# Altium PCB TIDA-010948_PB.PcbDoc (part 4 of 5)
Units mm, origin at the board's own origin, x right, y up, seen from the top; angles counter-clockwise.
Board outline 140 x 180 mm, 4 copper layers (Top Layer, Mid-Layer 1, Mid-Layer 2, Bottom Layer), stack 1.554 mm thick; 481 components, 274 nets, 1278 pads, 301 vias.
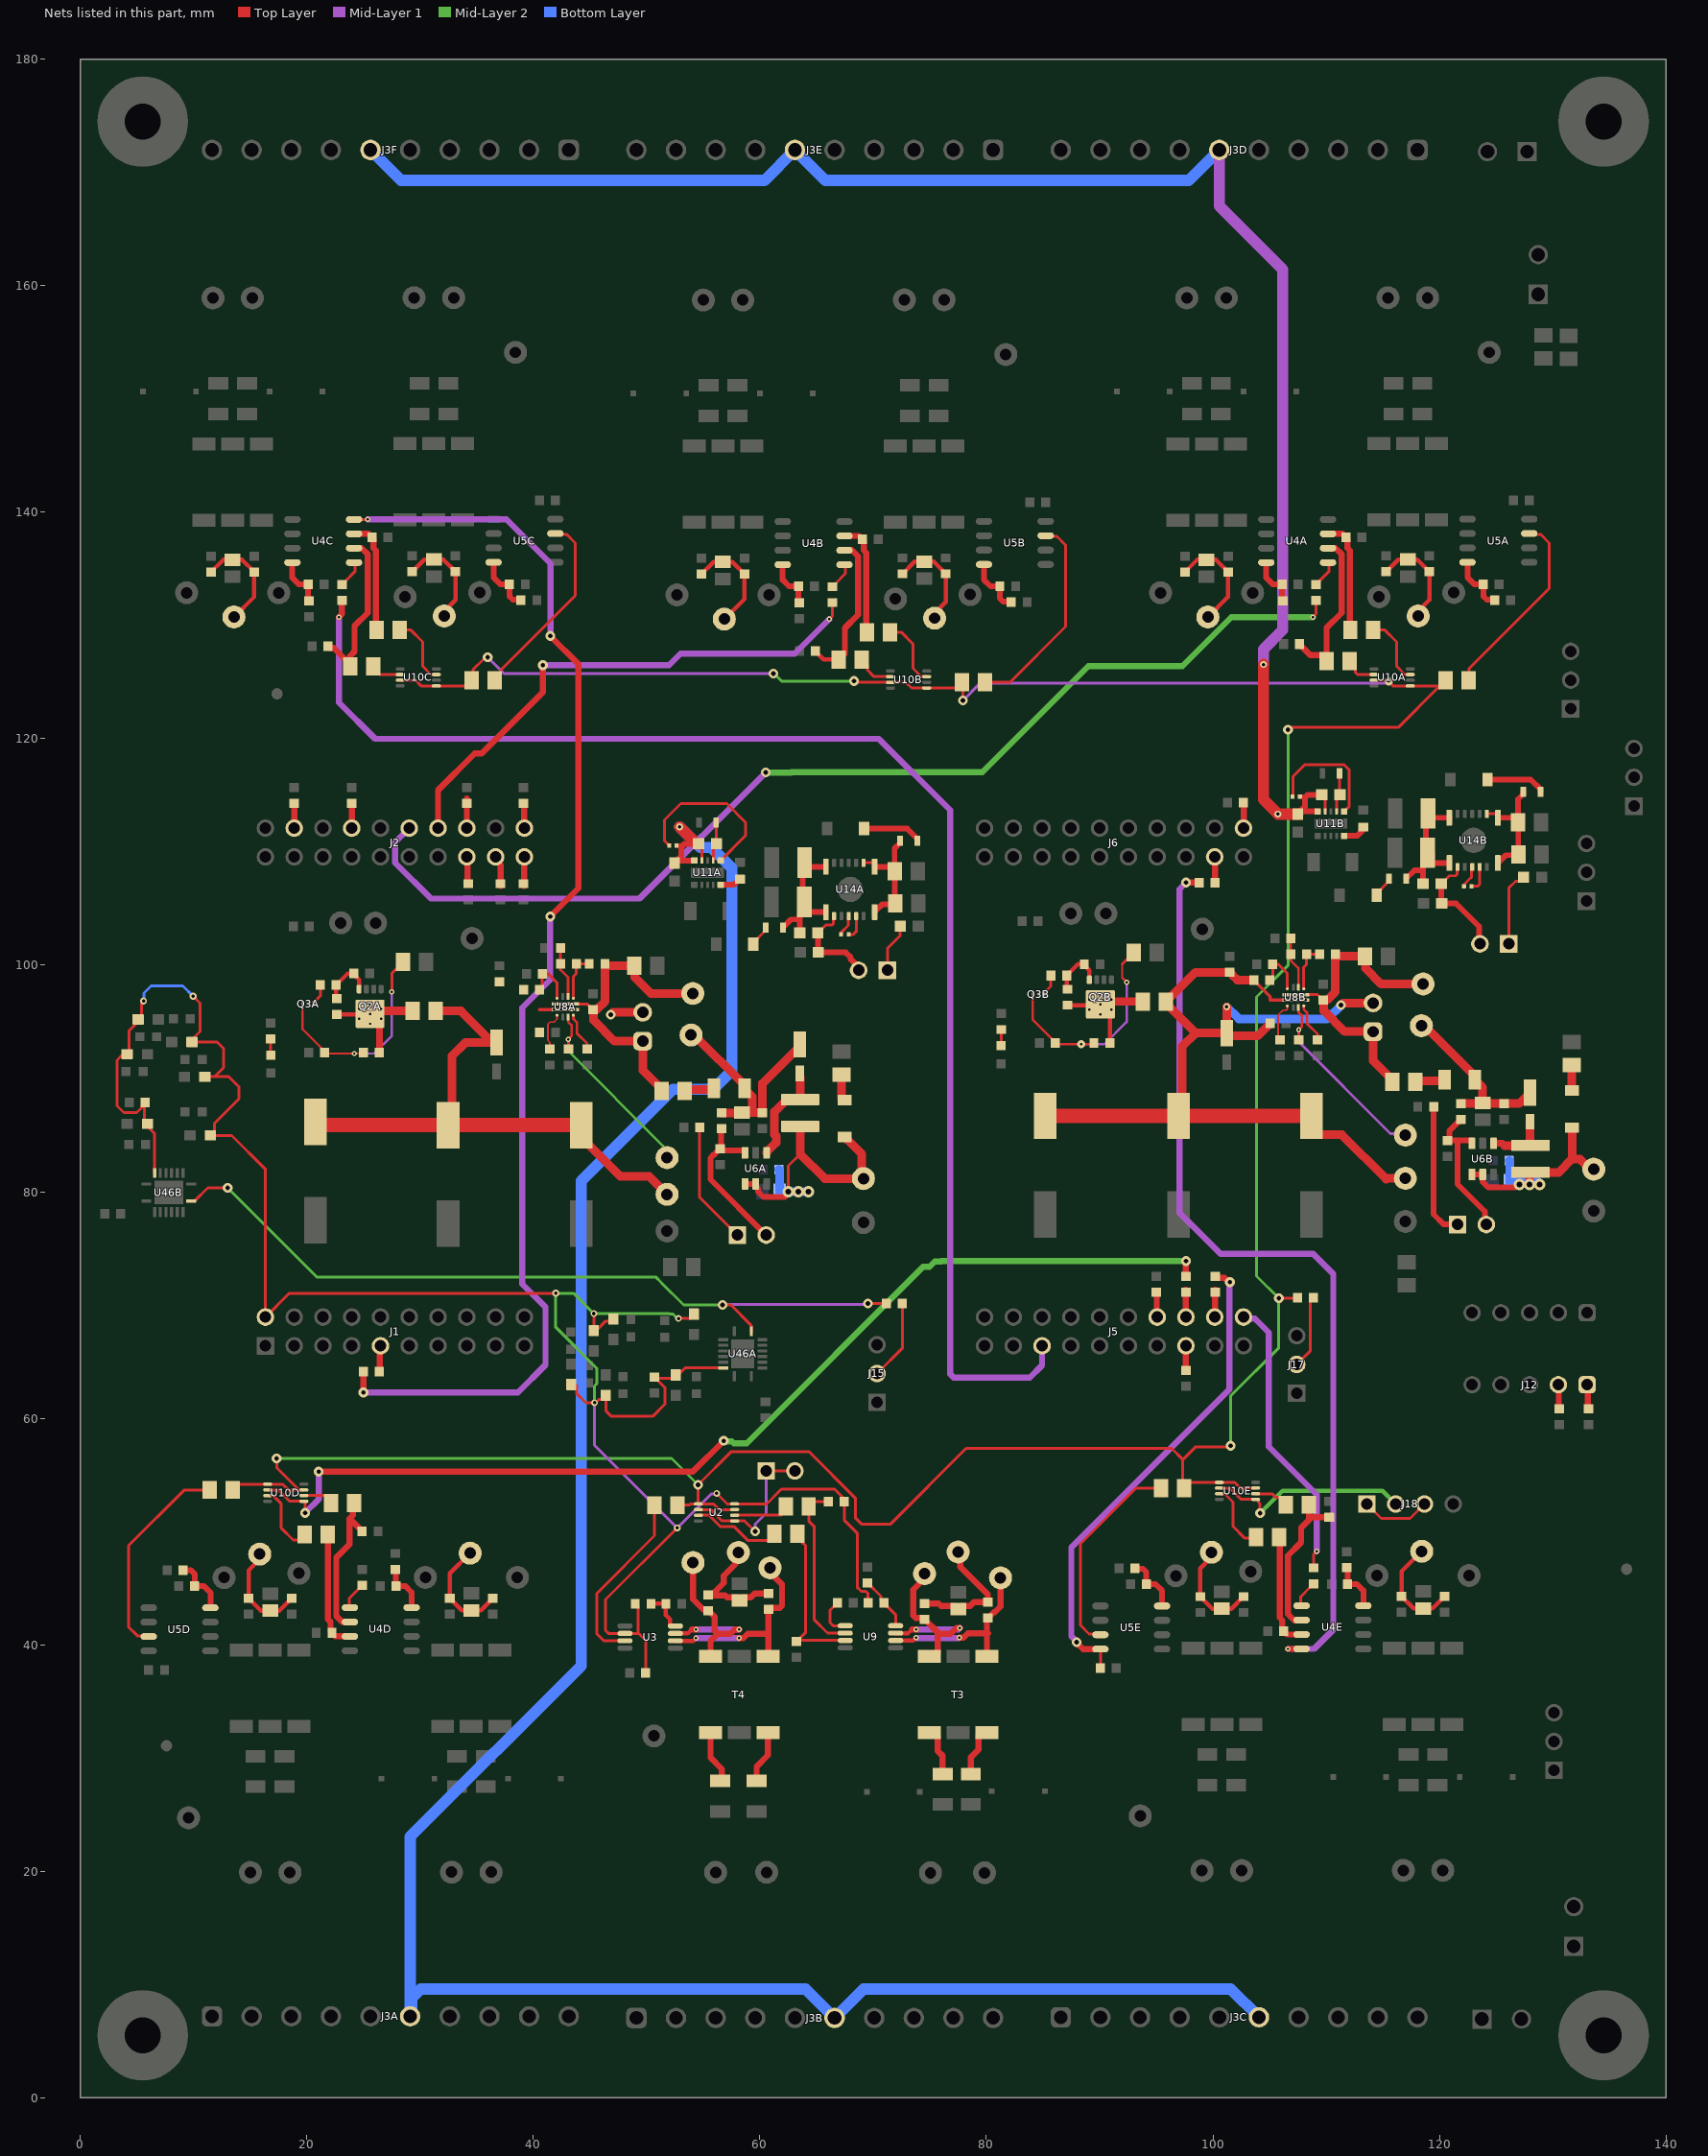
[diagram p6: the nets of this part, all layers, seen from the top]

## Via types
v1: diameter 0.457/0.457/0.457/0.457 (per signal layer), hole 0.203, Top Layer to Bottom Layer, tented both sides, 68 vias
v2: diameter 0.864, hole 0.406, Top Layer to Mid-Layer 1, 51 vias
v3: diameter 0.5, hole 0.2, Top Layer to Bottom Layer, 40 vias
v4: diameter 0.864, hole 0.406, Top Layer to Bottom Layer, 40 vias
v5: diameter 0.7, hole 0.3, Top Layer to Bottom Layer, 36 vias
v6: diameter 0.61, hole 0.3, Top Layer to Bottom Layer, 29 vias
v7: diameter 1.524, hole 0.762, Top Layer to Bottom Layer, tented both sides, 12 vias
v8: diameter 0.203, hole 0.203, Top Layer to Bottom Layer, tented both sides, 8 vias
v9: diameter 1.016, hole 0.508, Top Layer to Bottom Layer, tented both sides, 6 vias
v10: diameter 0.61, hole 0.3, Top Layer to Mid-Layer 1, 3 vias
v11: diameter 0.457, hole 0.203, Top Layer to Mid-Layer 1, tented both sides, 2 vias
v12: diameter 0.5, hole 0.2, Top Layer to Bottom Layer, tented both sides, 2 vias
v13: diameter 0.7, hole 0.203, Top Layer to Mid-Layer 1, tented both sides, 1 vias
v14: diameter 0.7, hole 0.254, Top Layer to Bottom Layer, 1 vias
v15: diameter 0.7, hole 0.254, Top Layer to Mid-Layer 1, 1 vias
v16: diameter 0.457/0.457 (per signal layer), hole 0.203, Top Layer to Mid-Layer 1, tented both sides, 1 vias

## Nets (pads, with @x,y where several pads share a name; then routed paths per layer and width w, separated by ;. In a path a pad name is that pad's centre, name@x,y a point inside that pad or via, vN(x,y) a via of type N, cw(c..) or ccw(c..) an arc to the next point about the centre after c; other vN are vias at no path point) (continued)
LP_5V0: C2A.1 C2B.1 J1.21 R1A.2 R1B.2 R2A.2 R2B.2 R3A.2 R3B.2 R4A.2 R4B.2 R5A.2 R5B.2 R6A.2 R6B.2 R10.2 R15.1 R30.1 R33.2 U2.8 U3.2 U46A.15 U46B.15 | length 204.2
  Top Layer w0.254: v6(5.568,96.847) 5.568,96.751 5.407,96.59 5.407,95.339 5.284,95.215 5.284,95.19 5.011,94.917 4.986,94.917 4.291,94.222 4.291,92.208 4.32,92.18 4.32,92.163 4.204,92.048 3.666,92.048 3.238,91.62 3.238,87.586 3.833,86.991 4.978,86.991 5.447,87.459 5.447,87.609 C2B.1@5.72,87.882 5.632,87.795 5.632,86.073 5.72,85.986 5.72,85.961 5.993,85.688 6.018,85.688 6.546,85.16 U46B.15@6.546,81.656 ; v6(9.947,97.263) 10.567,96.643 10.567,94.158 9.649,93.24 9.649,93.215 12.067,93.215 12.639,92.644 12.639,90.958 11.836,90.155 ; R5B.2@10.787,90.155 11.836,90.155 ; v6(41.975,71.035) 18.445,71.035 J1.21@16.337,68.927 16.337,81.973 13.357,84.953 11.488,84.953 R6B.2@11.471,84.97 11.503,84.97 11.826,85.293 11.826,86.037 13.999,88.21 13.999,89.265 13.109,90.155 11.836,90.155 ; R3A.2@43.335,63.178 43.608,62.905 43.799,62.905 43.799,62.185 44.621,61.364 45.486,61.364 45.763,61.641 46.072,61.641 46.395,61.964 R2A.2@46.395,62.214 ; v6(45.335,69.241) 45.335,67.543 45.36,67.543 45.992,68.176 45.992,68.201 46.343,68.551 R5A.2@47.065,68.551 ; R2A.2@46.42,62.214 46.42,60.628 46.888,60.161 50.524,60.161 51.63,61.267 51.63,62.676 C2A.1@50.78,63.527 ; R30.1@48.987,43.615 49.26,43.342 49.26,41.016 49.283,40.993 ; R33.2@49.912,37.525 49.912,40.364 49.283,40.993 ; R1A.2@52.564,63.814 52.564,63.639 R1A.2@52.589,63.614 ; v10(52.694,50.309) 46.37,43.985 46.37,41.257 46.635,40.993 U3.2@48.082,40.993 49.283,40.993 ; v6(52.807,68.807) 52.838,68.837 53.845,68.837 53.845,68.818 54.168,69.141 R6A.2@54.168,69.191 ; v10(56.186,53.357) 57.116,52.427 U2.8@57.766,52.427 60.602,52.427 61.9,53.725 66.595,53.725 R10.2@67.551,52.769 ; U46A.15@56.763,64.44 53.39,64.44 52.862,63.912 52.862,63.887 R1A.2@52.589,63.614 ; R10.2@67.444,52.637 67.444,50.993 68.59,49.847 68.59,45.066 68.943,44.713 69.34,44.713 69.553,44.501 R15.1@69.553,43.695 ; C2A.1@50.668,63.614 50.643,63.614 C2A.1@50.668,63.614 ; C2A.1@50.668,63.614 50.693,63.614 C2A.1@50.78,63.527 ; C2A.1@50.78,63.527 52.477,63.527 52.564,63.614 R1A.2@52.589,63.614
  Mid-Layer 1 w0.254: v6(45.39,61.364) 45.39,57.612 v10(52.694,50.309) 55.674,53.289 56.118,53.289 v10(56.186,53.357)
  Mid-Layer 2 w0.254: v6(45.39,61.364) 45.39,62.843 45.584,63.036 45.584,64.419 41.975,68.028 v6(41.975,71.035) 43.541,71.035 v6(45.335,69.241) 51.995,69.241 52.043,69.193 52.325,69.193 52.711,68.807 v6(52.807,68.807)
  Bottom Layer w0.254: v6(5.568,96.847) 5.609,96.888 5.609,97.533 6.244,98.168 9.042,98.168 v6(9.947,97.263)
LS_OE_HIGH: R11.1 U46A.8 U46B.8 | length 70.1
  Top Layer w0.254: U46B.8@9.771,79.181 10.063,79.181 11.23,80.348 v4(13,80.348) ; v4(56.694,69.994) 57.43,69.994 59.225,68.199 59.225,67.678 U46A.8@59.238,67.665 ; v2(69.541,70.133) R11.1@71.171,70.133
  Mid-Layer 1 w0.254: v4(56.694,69.994) 56.763,70.064 69.471,70.064 v2(69.541,70.133)
  Mid-Layer 2 w0.254: v4(13,80.348) 20.905,72.442 50.835,72.442 51.277,72 51.277,71.976 53.259,69.994 v4(56.694,69.994)
NetC8A_1: C8A.1 R16A.2 U4A.8 | length 4.3
  Top Layer w0.508: U4A.8@104.715,135.562 104.715,134.223 105.281,133.657 C8A.1@106.105,133.657 R16A.2@106.105,132.573 ; R16A.2@106.169,132.182 R16A.2@106.333,132.345
NetC8B_1: C8B.1 R16B.2 U4B.8 | length 4.3
  Top Layer w0.508: U4B.8@62.016,135.375 62.016,134.036 62.582,133.47 C8B.1@63.406,133.47 R16B.2@63.406,132.386 ; R16B.2@63.47,131.995 R16B.2@63.633,132.158
NetC8C_1: C8C.1 R16C.2 U4C.8 | length 4.3
  Top Layer w0.508: U4C.8@18.715,135.562 18.715,134.223 19.281,133.657 C8C.1@20.105,133.657 R16C.2@20.105,132.573 ; R16C.2@20.169,132.182 R16C.2@20.333,132.345
NetC8D_1: C8D.1 R16D.2 U4D.8 | length 4.3
  Top Layer w0.508: R16D.2@27.625,46.492 R16D.2@27.789,46.656 ; R16D.2@27.853,46.264 C8D.1@27.853,45.181 28.677,45.181 29.243,44.615 U4D.8@29.243,43.276
NetC8E_1: C8E.1 R16E.2 U4E.8 | length 4.3
  Top Layer w0.508: R16E.2@111.667,46.655 R16E.2@111.831,46.818 ; R16E.2@111.895,46.427 C8E.1@111.895,45.343 112.719,45.343 113.285,44.777 U4E.8@113.285,43.438
NetC9A_1: C9A.1 R18A.2 U5A.8 | length 5.2
  Top Layer w0.508: U5A.8@122.484,135.582 122.484,134.243 123.07,133.657 123.874,133.657 123.874,132.594 124.187,132.28 R18A.2@124.89,132.28
NetC9B_1: C9B.1 R18B.2 U5B.8 | length 5.2
  Top Layer w0.508: U5B.8@79.784,135.395 79.784,134.056 80.371,133.47 81.174,133.47 81.174,132.407 81.488,132.093 R18B.2@82.19,132.093
NetC9C_1: C9C.1 R18C.2 U5C.8 | length 5.2
  Top Layer w0.508: U5C.8@36.484,135.582 36.484,134.243 37.07,133.657 37.874,133.657 37.874,132.594 38.187,132.28 R18C.2@38.89,132.28
NetC9D_1: C9D.1 R18D.2 U5D.8 | length 5.2
  Top Layer w0.508: R18D.2@9.068,46.557 9.771,46.557 10.084,46.244 10.084,45.181 10.888,45.181 11.474,44.594 U5D.8@11.474,43.255
NetC9E_1: C9E.1 R18E.2 U5E.8 | length 5.2
  Top Layer w0.508: R18E.2@93.11,46.72 93.813,46.72 94.126,46.406 94.126,45.343 94.93,45.343 95.516,44.757 U5E.8@95.516,43.418
NetC10A_1: C10A.1 R22A.1 R24A.1 TP21A.1 | length 9.4
  Top Layer w0.381: R22A.1@97.534,134.735 98.603,135.804 C10A.1@99.439,135.804 100.276,135.804 R24A.1@101.344,134.735 101.345,132.536 TP21A.1@99.545,130.736
NetC10B_1: C10B.1 R22B.1 R24B.1 TP21B.1 | length 9.4
  Top Layer w0.381: R22B.1@54.835,134.548 55.904,135.617 56.74,135.617 57.576,135.617 58.645,134.548 58.645,132.349 TP21B.1@56.845,130.549
NetC10C_1: C10C.1 R22C.1 R24C.1 TP21C.1 | length 9.4
  Top Layer w0.381: R22C.1@11.534,134.735 12.603,135.804 C10C.1@13.439,135.804 14.276,135.804 R24C.1@15.344,134.735 15.345,132.536 TP21C.1@13.545,130.736
NetC10D_1: C10D.1 R22D.1 R24D.1 TP21D.1 | length 9.4
  Top Layer w0.381: TP21D.1@34.413,48.102 32.613,46.302 R24D.1@32.614,44.103 33.682,43.034 C10D.1@34.519,43.034 35.355,43.034 R22D.1@36.424,44.103
NetC10E_1: C10E.1 R22E.1 R24E.1 TP21E.1 | length 9.4
  Top Layer w0.381: TP21E.1@118.455,48.264 116.655,46.464 116.655,44.265 117.724,43.196 118.56,43.196 119.397,43.196 R22E.1@120.466,44.265
NetC11A_1: C11A.1 R23A.1 R25A.1 TP22A.1 | length 9
  Top Layer w0.381: R23A.1@115.302,134.755 116.371,135.824 C11A.1@117.208,135.824 118.044,135.824 R25A.1@119.113,134.755 119.113,132.272 118.126,131.285 TP22A.1@118.126,130.838
NetC11B_1: C11B.1 R23B.1 R25B.1 TP22B.1 | length 9
  Top Layer w0.381: R23B.1@72.603,134.568 73.672,135.637 C11B.1@74.508,135.637 75.344,135.637 R25B.1@76.413,134.568 76.413,132.085 75.426,131.098 TP22B.1@75.426,130.651
NetC11C_1: C11C.1 R23C.1 R25C.1 TP22C.1 | length 9
  Top Layer w0.381: R23C.1@29.302,134.755 30.371,135.824 C11C.1@31.208,135.824 32.044,135.824 R25C.1@33.113,134.755 33.113,132.272 32.126,131.285 TP22C.1@32.126,130.838
NetC11D_1: C11D.1 R23D.1 R25D.1 TP22D.1 | length 9
  Top Layer w0.381: TP22D.1@15.832,47.999 15.832,47.552 14.845,46.565 R25D.1@14.845,44.082 15.914,43.013 C11D.1@16.75,43.013 17.587,43.013 R23D.1@18.656,44.082
NetC11E_1: C11E.1 R23E.1 R25E.1 TP22E.1 | length 9
  Top Layer w0.381: TP22E.1@99.874,48.162 99.874,47.715 98.887,46.728 R25E.1@98.887,44.245 99.956,43.176 C11E.1@100.792,43.176 101.629,43.176 R23E.1@102.698,44.245
NetC18A_1: C18A.1 C116A.1 D1A.1 L5A.1 TP27A.1 U6A.4 U6A.5 | length 26.6
  Top Layer w0.254: 62.213,79.535 62.603,79.925 v9(62.51,80.017) 62.51,82.288 63.56,83.337
  Top Layer w0.508: U6A.4@58.68,80.692 U6A.5@59.63,80.692 59.63,80.492 59.826,80.296 59.826,80.034 60.325,79.535 62.213,79.535
  Top Layer w0.762: L5A.1@63.56,85.765 63.56,83.337 65.736,81.161 TP27A.1@69.141,81.161 68.992,81.311 68.992,83.32 67.716,84.597 67.716,84.749 67.639,84.826 D1A.1@67.487,84.826
  Bottom Layer w0.762: C18A.1@61.671,81.938 61.721,81.888 C116A.1@61.721,80.035 ; C116A.1@61.721,80.008 v9(64.288,80.008)
  other v9: 63.399,80.017
NetC18B_1: C18B.1 C116B.1 D1B.1 L5B.1 TP27B.1 U6B.4 U6B.5 | length 19.5
  Top Layer w0.508: U6B.4@122.877,81.52 U6B.5@123.827,81.52 123.827,80.875 124.338,80.363 v9@126.706,80.363
  Top Layer w0.762: v9(127.964,80.641) 127.964,81.621 L5B.1@128.053,81.71 130.551,81.71 131.726,82.886 ; D1B.1@131.726,85.654 131.726,82.886 ; TP27B.1@133.635,81.99 133.291,81.99 132.395,82.886 131.726,82.886
  Bottom Layer w0.762: C18B.1@126.164,82.767 126.214,82.717 C116B.1@126.214,80.863 ; C116B.1@126.214,80.837 v9@128.782,80.837
  other v9: 127.075,80.641 128.853,80.633
NetC21_2: C21.2 T3.6 | length 4.5
  Top Layer w0.54: C21.2@78.617,28.582 78.617,30.049 79.302,30.734 79.302,31.922 79.604,32.223 T3.6@80.048,32.223
NetC22A_1: C22A.1 C120A.1 D3A.1 R28A.2 R31A.1 TP30A.1 | length 20.2
  Top Layer w0.762: TP30A.1@53.919,93.841 54.187,93.841 58.651,89.377 R31A.1@58.651,89.138 ; R28A.2@56.616,86.958 58.371,86.958 C120A.1@58.421,87.008 59.331,87.008 59.331,88.372 R31A.1@58.651,89.052 ; 59.331,86.977 60.207,86.977 C22A.1@60.226,86.958 60.226,89.565 63.524,92.863 D3A.1@63.524,93.008
NetC22B_1: C22B.1 C120B.1 D3B.1 R28B.2 R31B.1 TP30B.1 | length 16
  Top Layer w0.762: TP30B.1@118.562,94.52 TP30B.1@118.413,94.67 118.681,94.67 123.145,90.205 R31B.1@123.145,89.88 123.824,89.201 C120B.1@123.824,87.836 ; R28B.2@121.922,87.786 123.774,87.786 C120B.1@123.824,87.836 ; D3B.1@128.018,88.754 127.05,87.786 C22B.1@125.732,87.786 123.874,87.786 C120B.1@123.824,87.836
NetC23_2: C23.2 T3.4 | length 4.4
  Top Layer w0.54: T3.4@74.968,32.223 75.413,32.223 75.714,31.922 75.714,30.605 76.14,30.179 C23.2@76.14,28.582
NetC24A_1: C24A.1 J11A.1 NT1A.2 NT6A.2 R37A.2 TP33A.1 U8A.5 | length 27.5
  Top Layer w0.254: U8A.5@42.831,96.584 44.736,96.584 45.236,96.084 C24A.1@45.261,96.084
  Top Layer w0.762: C24A.1@45.305,96.065 45.305,95.152 47.154,93.303 J11A.1@49.647,93.303 49.647,90.739 51.339,89.048 NT6A.2@51.339,88.883 ; C24A.1@45.605,96.103 46.321,96.819 R37A.2@46.321,100.119 ; R37A.2@46.321,100.144 R37A.2@46.321,100.119 ; TP33A.1@54.073,97.512 50.376,97.512 48.964,98.924 48.964,99.913 NT1A.2@48.921,99.955 46.486,99.955 R37A.2@46.321,100.119
NetC24B_1: C24B.1 J11B.1 NT1B.2 NT6B.2 R37B.2 TP33B.1 U8B.5 | length 27.5
  Top Layer w0.254: U8B.5@107.325,97.412 109.23,97.412 109.73,96.912 C24B.1@109.755,96.912
  Top Layer w0.762: C24B.1@109.799,96.893 109.799,95.98 111.648,94.131 J11B.1@114.141,94.131 114.141,91.568 115.832,89.877 NT6B.2@115.832,89.711 ; C24B.1@110.099,96.931 110.815,97.647 R37B.2@110.815,100.948 ; R37B.2@110.815,100.973 R37B.2@110.815,100.948 ; TP33B.1@118.566,98.34 114.869,98.34 113.457,99.752 113.457,100.741 NT1B.2@113.415,100.783 110.979,100.783 R37B.2@110.815,100.948
NetC25A_1: C25A.1 U8A.10 | length 3.5
  Top Layer w0.229: U8A.10@43.531,95.584 43.531,95.275 43.831,94.975 43.831,94.003 44.736,93.098 C25A.1@44.736,92.589
NetC25B_1: C25B.1 U8B.10 | length 3.5
  Top Layer w0.229: U8B.10@108.025,96.412 108.025,96.103 108.325,95.803 108.325,94.831 109.23,93.926 C25B.1@109.23,93.417
NetC26A_1: C26A.1 U8A.7 | length 3.6
  Top Layer w0.152: C26A.1@41.439,92.589 41.439,93.199 41.278,93.36 41.278,93.662 41.277,93.663 41.277,94.449 41.278,94.45 41.278,94.805 41.448,94.975 41.803,94.975 42.081,95.253 U8A.7@42.081,95.586
NetC26B_1: C26B.1 U8B.7 | length 3.6
  Top Layer w0.152: C26B.1@105.933,93.417 105.756,93.594 105.756,95.593 106.199,96.036 106.486,96.036 106.575,96.125 U8B.7@106.575,96.412
NetC27A_2: C27A.2 Q2A.4 R44A.1 R46A.2 | length 4.8
  Top Layer w0.381: R44A.1@22.651,97.053 22.589,97.115 R46A.2@22.589,98.258 23.605,99.274 C27A.2@24.05,99.274 ; C27A.2@24.15,99.274 C27A.2@24.05,99.274 ; Q2A.4@24.597,97.893 24.597,98.727 C27A.2@24.05,99.274
NetC27B_2: C27B.2 Q2B.4 R44B.1 R46B.2 | length 4.8
  Top Layer w0.381: R44B.1@87.144,97.882 87.082,97.944 R46B.2@87.082,99.087 88.098,100.103 C27B.2@88.544,100.103 ; C27B.2@88.644,100.103 C27B.2@88.544,100.103 ; Q2B.4@89.09,98.722 89.09,99.556 C27B.2@88.544,100.103
NetC32_1: C32.1 R21.1 R27.1 TP5.1 | length 11.6
  Top Layer w0.54: R27.1@74.522,43.64 75.771,43.64 76.001,43.41 77.244,43.41 C32.1@77.51,43.144 77.79,43.424 78.561,43.424 78.897,43.76 R21.1@80.131,43.76 ; TP5.1@77.51,48.186 77.693,48.003 77.693,46.868 80.132,44.43 R21.1@80.131,43.76
NetC33_1: C33.1 R15.2 U9.8 | length 4.8
  Top Layer w0.254: C33.1@69.482,45.462 69.507,45.462 70.68,44.288 70.68,43.968 R15.2@70.953,43.695 70.953,43.67 71.978,42.645 U9.8@71.978,41.67
NetC34_2: C34.2 T4.6 | length 4.7
  Top Layer w0.54: C34.2@59.709,27.98 59.709,29.231 60.715,30.237 T4.6@60.715,32.218
NetC35_2: C35.2 T4.4 | length 4.7
  Top Layer w0.54: T4.4@55.635,32.218 55.635,30.033 56.645,29.024 56.645,28.136 C35.2@56.488,27.98
NetC36_1: C36.1 R34.1 R35.1 TP11.1 | length 10.5
  Top Layer w0.54: R35.1@55.437,44.39 55.472,44.355 55.755,44.355 56.915,44.355 57.101,44.17 57.922,44.17 C36.1@58.202,43.889 58.482,44.17 59.198,44.17 59.533,44.505 R34.1@60.768,44.505 ; R35.1@55.755,44.39 56.801,45.437 56.801,46.092 57.827,47.118 57.827,47.867 TP11.1@58.102,48.142
NetC37_1: C37.1 R30.2 U3.8 | length 3.9
  Top Layer w0.381: R30.2@50.387,43.615 C37.1@51.699,43.615 51.699,42.618 52.068,42.249 52.068,41.675 52.1,41.643 U3.8@52.532,41.643
NetC46A_2: C46A.2 U11A.5 | length 1.9
  Top Layer w0.508: U11A.5@56.536,107.105 57.689,107.105 58.183,107.599 C46A.2@58.233,107.599
NetC46B_2: C46B.2 U11B.5 | length 1.9
  Top Layer w0.508: U11B.5@111.583,111.432 112.736,111.432 113.23,111.926 C46B.2@113.28,111.926
NetC50A_2: C50A.2 C51A.2 R51A.1 U14A.1 U14A.2 U14A.14 | length 11.2
  Top Layer w0.254: U14A.2@69.153,109.047 70.005,109.047 70.128,108.924 U14A.1@70.128,108.697
  Top Layer w0.5: U14A.14@70.128,104.697 70.826,105.396 72.013,105.396 71.915,105.493 71.915,108.277 C51A.2@71.892,108.3 C51A.2@71.892,108.312 ; U14A.1@70.128,108.697 71.507,108.697 C51A.2@71.892,108.312 ; R51A.1@72.371,110.992 72.371,110.802 71.892,110.323 C51A.2@71.892,108.312
NetC50B_2: C50B.2 C51B.2 R51B.1 U14B.1 U14B.2 U14B.14 | length 11.2
  Top Layer w0.254: U14B.2@124.199,113.374 125.051,113.374 125.174,113.251 U14B.1@125.174,113.024
  Top Layer w0.5: U14B.14@125.174,109.024 125.873,109.723 127.06,109.723 126.962,109.821 126.962,112.604 C51B.2@126.939,112.628 C51B.2@126.939,112.639 ; U14B.1@125.174,113.024 126.554,113.024 C51B.2@126.939,112.639 ; R51B.1@127.417,115.32 127.417,115.129 126.939,114.65 C51B.2@126.939,112.639
NetC59A_1: C59A.1 C60A.2 R41A.2 R52A.2 U14A.7 U14A.8 | length 12.3
  Top Layer w0.5: R52A.2@62.032,103.333 62.748,104.049 63.51,104.049 ; R41A.2@63.51,102.866 63.51,104.049 ; C60A.2@63.775,105.988 C59A.1@63.775,108.697 ; C60A.2@63.92,105.819 C60A.2@63.92,105.606 ; C59A.1@63.986,108.697 U14A.7@65.828,108.697 ; U14A.8@65.828,104.697 64.321,104.697 64.308,105.606 C60A.2@63.92,105.606 ; 63.51,104.049 63.51,104.496 63.92,104.906 C60A.2@63.92,105.606
NetC59B_1: C59B.1 C60B.2 R41B.2 R52B.2 U14B.7 U14B.8 | length 12.3
  Top Layer w0.5: R52B.2@117.079,107.661 117.794,108.376 118.557,108.376 ; R41B.2@118.557,107.193 118.557,108.376 ; C60B.2@118.822,110.316 C59B.1@118.822,113.024 ; C60B.2@118.967,110.146 C60B.2@118.967,109.934 ; C59B.1@119.032,113.024 U14B.7@120.874,113.024 ; U14B.8@120.874,109.024 119.367,109.024 119.354,109.934 C60B.2@118.967,109.934 ; 118.557,108.376 118.557,108.824 118.967,109.234 C60B.2@118.967,109.934
NetD1A_2: D1A.2 NT4A.2 | length 2.5
  Top Layer w0.762: NT4A.2@67.19,90.355 67.19,90.122 67.212,90.101 67.212,88.223 67.334,88.101 D1A.2@67.487,88.101
NetD1B_2: D1B.2 NT4B.2 | length 2.3
  Top Layer w0.762: NT4B.2@131.684,91.183 131.705,91.162 131.705,88.951 D1B.2@131.726,88.929
NetD2A_2: D2A.2 R52A.1 | length 1.9
  Top Layer w0.254: D2A.2@59.422,101.861 59.422,102.014 60.381,102.973 60.381,103.206 R52A.1@60.508,103.333
NetD2B_2: D2B.2 R52B.1 | length 1.9
  Top Layer w0.254: D2B.2@114.468,106.189 114.468,106.341 115.428,107.3 115.428,107.534 R52B.1@115.555,107.661
NetD3A_2: D3A.2 L5A.2 U6A.1 | length 9.1
  Top Layer w0.762: U6A.1@60.58,83.442 60.58,83.48 61.424,84.324 61.424,84.917 61.279,85.063 61.279,87.064 62.35,88.135 L5A.2@63.56,88.135 63.56,90.11 63.524,90.145 D3A.2@63.524,90.448
NetD3B_2: D3B.2 L5B.2 U6B.1 | length 5.5
  Top Layer w0.6: U6B.1@124.777,84.27 125.548,84.27
  Top Layer w0.635: 125.548,84.27 125.738,84.08
  Top Layer w0.762: 125.738,84.08 L5B.2@128.053,84.08 128.018,84.116 D3B.2@128.018,86.194
NetD6A_1: D6A.1 R51A.2 | length 5.2
  Top Layer w0.508: D6A.1@69.21,112.072 73.006,112.072 73.895,111.183 R51A.2@73.895,110.992
NetD6B_1: D6B.1 R51B.2 | length 5.2
  Top Layer w0.508: D6B.1@124.256,116.399 128.052,116.399 128.941,115.51 R51B.2@128.941,115.32
NetD8A_2: D8A.2 R49A.1 | length 1.4
  Top Layer w0.254: D8A.2@16.809,92.073 R49A.1@16.809,93.494
NetD8B_2: D8B.2 R49B.1 | length 1.4
  Top Layer w0.254: D8B.2@81.303,92.902 R49B.1@81.302,94.323
NetJ1_5: J1.5 R50.2 | length 2.3
  Top Layer w0.54: R50.2@26.384,64.129 26.441,64.185 26.441,66.331 J1.5@26.497,66.387
NetJ2_11: J2.11 R57.1 | length 2.2
  Top Layer w0.54: R57.1@39.135,114.29 39.166,114.259 39.166,112.138 J2.11@39.197,112.107
NetJ2_13: J2.13 R54.1 | length 2.6
  Top Layer w0.54: J2.13@34.117,112.107 34.117,114.734
NetJ2_17: J2.17 R32.1 | length 2.2
  Top Layer w0.54: J2.17@23.957,112.107 R32.1@23.957,114.29
NetJ2_19: J2.19 R14.1 | length 2.2
  Top Layer w0.54: J2.19@18.877,112.107 18.879,112.109 R14.1@18.879,114.287
NetJ2_31: J2.31 R56.2 | length 2.6
  Top Layer w0.54: R56.2@39.135,106.987 39.166,107.018 39.166,109.536 J2.31@39.197,109.567
NetJ2_32: J2.32 R55.2 | length 2.8
  Top Layer w0.54: J2.32@36.657,109.567 36.657,109.293 37.094,108.856 R55.2@37.094,106.986
NetJ2_33: J2.33 R53.2 | length 2.4
  Top Layer w0.54: J2.33@34.117,109.567 34.18,109.504 34.18,107.262 R53.2@34.242,107.199
NetJ5_48: J5.48 R59.2 | length 2.2
  Top Layer w0.54: R59.2@97.617,64.216 J5.48@97.617,66.387
NetJ5_67: J5.67 R58.1 | length 2.2
  Top Layer w0.54: R58.1@95.01,71.111 95.043,71.078 95.043,68.961 J5.67@95.077,68.927
NetJ5_68: J5.68 R60.1 | length 2.4
  Top Layer w0.54: J5.68@97.617,68.927 R60.1@97.617,71.362
NetJ5_69: J5.69 R61.1 | length 2.5
  Top Layer w0.54: J5.69@100.157,68.927 100.182,68.952 100.182,71.337 R61.1@100.207,71.362
NetJ6_51: J6.51 R63.1 | length 2.3
  Top Layer w0.54: J6.51@102.697,112.107 102.721,112.131 102.721,114.324 102.696,114.349 R63.1@102.7,114.353
NetJ6_72: J6.72 R62.2 | length 2.3
  Top Layer w0.54: J6.72@100.157,109.567 100.177,109.547 R62.2@100.177,107.316
NetJ9A_1: J9A.1 R7A.2 | length 4.4
  Top Layer w0.254: J9A.1@71.254,99.556 71.254,101.479 72.392,102.617 R7A.2@72.392,103.443
NetJ9A_2: J9A.2 R41A.1 R143A.2 U14A.9 | length 8.6
  Top Layer w0.254: R41A.1@65.11,102.866 65.135,102.866 65.842,103.573 66.39,103.573 66.505,103.687 66.505,104.299 U14A.9@66.553,104.347
  Top Layer w0.508: R41A.1@65.135,102.841 65.135,101.161 R143A.2@65.16,101.136 67.574,101.136 68.027,100.684 68.027,100.525 68.714,99.838 J9A.2@68.714,99.556
NetJ9B_1: J9B.1 R7B.2 | length 6.6
  Top Layer w0.254: J9B.1@126.121,101.887 126.121,106.814 126.73,107.423 127.09,107.423 R7B.2@127.438,107.771
NetJ9B_2: J9B.2 R41B.1 R143B.2 U14B.9 | length 9.8
  Top Layer w0.254: R41B.1@120.157,107.193 120.182,107.193 120.889,107.9 121.437,107.9 121.551,108.015 121.551,108.626 U14B.9@121.599,108.674
  Top Layer w0.508: R41B.1@120.182,107.168 120.182,105.489 R143B.2@120.207,105.464 121.469,105.464 123.508,103.424 123.508,101.96 J9B.2@123.581,101.887
NetJ12_1: J12.1 R64.1 | length 2.2
  Top Layer w0.54: J12.1@133.05,62.958 133.106,62.901 133.106,60.878 R64.1@133.163,60.821
NetJ12_2: J12.2 R65.1 | length 2.2
  Top Layer w0.54: J12.2@130.51,62.958 130.54,62.927 130.54,60.852 R65.1@130.571,60.821
NetJ15_2: J15.2 R11.2 | length 7.1
  Top Layer w0.254: J15.2@70.338,63.946 72.6,66.208 72.6,70.105 R11.2@72.571,70.133
NetJ17_2: J17.2 R12.2 | length 6.9
  Top Layer w0.254: J17.2@107.398,64.743 108.615,65.961 108.61,67.988 108.61,70.368 R12.2@108.883,70.641 R12.2@109.156,70.368
NetJ18_1: J18.1 J18.3 | length 6.1
  Top Layer w0.254: J18.1@113.606,52.42 114.876,51.15 117.416,51.15 J18.3@118.686,52.42
NetJ26A_1: J26A.1 R13A.2 | length 10.9
  Top Layer w0.254: R13A.2@54.674,85.663 54.674,79.507 J26A.1@58.009,76.171
NetJ26A_2: J26A.2 R26A.2 R28A.1 U6A.3 | length 14.3
  Top Layer w0.508: R28A.1@56.616,85.558 56.558,85.499 56.558,83.836 R26A.2@56.499,83.777 ; U6A.3@58.68,83.442 58.68,83.585 58.634,83.631 56.645,83.631 R26A.2@56.499,83.777 ; J26A.2@60.549,76.171 55.62,81.1 55.62,82.965 55.927,83.272 55.969,83.272 56.474,83.777 R26A.2@56.499,83.777
NetJ26B_1: J26B.1 R13B.2 | length 12
  Top Layer w0.508: R13B.2@119.491,87.501 119.491,78.011 120.361,77.141 121.559,77.141 J26B.1@121.6,77.1
NetJ26B_2: J26B.2 R26B.2 R28B.1 U6B.3 | length 13.3
  Top Layer w0.508: 121.893,84.517 121.585,84.517 ; 121.894,84.516 122.831,84.516 122.877,84.47 U6B.3@122.877,84.27 ; R28B.1@121.922,86.386 121.897,86.386 120.877,85.367 120.877,84.663 120.731,84.517 R26B.2@120.706,84.517 121.585,84.517 ; J26B.2@124.14,77.1 124.018,77.222 124.018,78.245 121.585,80.677 121.585,84.517
NetNT2A_2: NT2A.2 U5A.3 | length 17.2
  Top Layer w0.254: NT2A.2@122.568,125.172 122.62,125.224 122.62,126.204 129.7,133.283 129.7,137.287 128.93,138.056 128,138.056 U5A.3@127.934,138.122
NetNT2B_2: NT2B.2 U5B.3 | length 18.5
  Top Layer w0.254: NT2B.2@79.868,124.985 82.083,124.985 87,129.901 87,137.1 86.231,137.869 85.3,137.869 U5B.3@85.234,137.935
NetNT2C_2: NT2C.2 U5C.3 | length 17.2
  Top Layer w0.254: NT2C.2@36.568,125.172 37.076,125.68 37.076,126.029 43.7,132.653 43.7,137.287 42.93,138.056 42,138.056 U5C.3@41.934,138.122
NetNT2D_2: NT2D.2 U5D.3 | length 18.5
  Top Layer w0.254: U5D.3@6.024,40.715 5.958,40.781 5.027,40.781 4.258,41.551 4.258,48.749 9.175,53.666 NT2D.2@11.39,53.666
NetNT2E_2: NT2E.2 U5E.3 | length 18.5
  Top Layer w0.254: U5E.3@90.066,40.878 90,40.944 89.07,40.944 88.3,41.713 88.3,48.912 93.217,53.828 NT2E.2@95.432,53.828
NetNT3A_1: NT3A.1 U10A.6 | length 2.9
  Top Layer w0.254: NT3A.1@112.073,126.875 112.581,126.367 112.581,125.86 112.77,125.672 U10A.6@114.227,125.672
NetNT3A_2: NT3A.2 R8A.1 U4A.2 | length 14.4
  Top Layer w0.54: R8A.1@107.65,128.364 107.65,128.339 108.597,127.392 109.676,127.392 NT3A.2@110.041,127.027 ; NT3A.2@110.041,126.875 NT3A.2@110.041,127.027 ; U4A.2@110.165,136.832 110.177,136.843 110.824,136.843 111.36,136.307 111.36,131.132 110.041,129.813 NT3A.2@110.041,127.027
NetNT3B_1: NT3B.1 U10B.6 | length 3.4
  Top Layer w0.254: NT3B.1@68.999,127.001 69.488,126.512 69.488,126.067 70.07,125.485 U10B.6@71.528,125.485
NetNT3B_2: NT3B.2 R8B.1 U4B.2 | length 12.9
  Top Layer w0.381: R8B.1@64.881,127.753 64.881,127.728 65.608,127.001 NT3B.2@66.967,127.001
  Top Layer w0.54: U4B.2@67.466,136.645 67.477,136.656 68.125,136.656 68.66,136.12 68.66,130.945 67.503,129.787 NT3B.2@67.503,127.518
NetNT3C_1: NT3C.1 U10C.6 | length 2.8
  Top Layer w0.254: NT3C.1@25.84,126.409 25.84,126.244 26.412,125.672 U10C.6@28.227,125.672
NetNT3C_2: NT3C.2 R8C.1 U4C.2 | length 14.6
  Top Layer w0.54: R8C.1@21.844,128.181 21.844,128.156 21.974,128.025 22.357,128.025 NT3C.2@23.808,126.574 ; NT3C.2@23.808,126.409 NT3C.2@23.808,126.574 ; U4C.2@24.165,136.832 24.177,136.843 24.824,136.843 25.36,136.307 25.36,131.132 24.202,129.974 24.202,127.705 23.808,127.311 NT3C.2@23.808,126.574
NetNT3D_1: NT3D.1 U10D.6 | length 2.7
  Top Layer w0.254: U10D.6@19.731,53.166 21.622,53.166 22.13,52.658 NT3D.1@22.13,52.519
NetNT3D_2: NT3D.2 R8D.1 U4D.2 | length 13.7
  Top Layer w0.54: U4D.2@23.793,42.006 23.781,41.994 23.134,41.994 22.598,42.53 22.598,47.706 23.755,48.863 23.755,51.132 ; NT3D.2@24.162,52.519 24.044,52.402 24.044,51.421 23.755,51.132 ; R8D.1@24.878,50.008 24.878,50.033 23.778,51.132 23.755,51.132
NetNT3E_1: NT3E.1 U10E.6 | length 3.2
  Top Layer w0.254: U10E.6@103.773,53.328 105.23,53.328 105.53,53.028 105.933,53.028 106.441,52.52 NT3E.1@106.441,52.355
NetNT3E_2: NT3E.2 R8E.1 U4E.2 | length 13.8
  Top Layer w0.54: U4E.2@107.835,42.168 107.823,42.157 107.176,42.157 106.64,42.693 106.64,47.868 107.798,49.026 107.798,50.322 108.473,50.998 ; NT3E.2@108.473,52.355 108.473,50.998 ; R8E.1@110.273,51.255 108.731,51.255 108.473,50.998
NetNT5A_1: NT5A.1 U10A.3 | length 6.1
  Top Layer w0.254: NT5A.1@114.169,129.599 115.178,129.599 116.222,128.555 116.222,126.404 116.946,125.68 117.418,125.68 U10A.3@117.427,125.672
NetNT5A_2: NT5A.2 R20A.2 U4A.3 | length 10
  Top Layer w0.54: U4A.3@110.165,138.102 111.46,138.102 111.744,137.818 R20A.2@111.744,137.793 111.874,137.663 111.874,136.839 112.1,136.614 112.1,129.713 NT5A.2@112.04,129.653
NetNT5B_1: NT5B.1 U10B.3 | length 6.1
  Top Layer w0.254: NT5B.1@71.469,129.412 72.479,129.412 73.523,128.368 73.523,126.217 74.246,125.493 74.719,125.493 U10B.3@74.728,125.485
NetNT5B_2: NT5B.2 R20B.2 U4B.3 | length 10
  Top Layer w0.54: U4B.3@67.466,137.915 68.76,137.915 69.044,137.631 R20B.2@69.044,137.606 69.174,137.476 69.174,136.652 69.4,136.427 69.4,129.526 NT5B.2@69.34,129.466
NetNT5C_1: NT5C.1 U10C.3 | length 6.1
  Top Layer w0.254: NT5C.1@28.169,129.599 29.178,129.599 30.222,128.555 30.222,126.404 30.946,125.68 31.418,125.68 U10C.3@31.427,125.672
NetNT5C_2: NT5C.2 R20C.2 U4C.3 | length 10
  Top Layer w0.54: U4C.3@24.165,138.102 25.46,138.102 25.744,137.818 R20C.2@25.744,137.793 25.874,137.663 25.874,136.839 26.1,136.614 26.1,129.713 NT5C.2@26.04,129.653
NetNT5D_1: NT5D.1 U10D.3 | length 6.4
  Top Layer w0.254: U10D.3@16.531,53.166 16.539,53.157 17.012,53.157 17.735,52.434 17.735,50.283 18.78,49.238 19.308,49.238 NT5D.1@19.803,49.733
NetNT5D_2: NT5D.2 R20D.2 U4D.3 | length 10
  Top Layer w0.54: NT5D.2@21.918,49.184 21.858,49.124 21.858,42.224 22.084,41.998 22.084,41.175 R20D.2@22.214,41.045 22.214,41.02 22.498,40.736 U4D.3@23.793,40.736
NetNT5E_1: NT5E.1 U10E.3 | length 6.2
  Top Layer w0.254: U10E.3@100.573,53.328 100.582,53.32 101.054,53.32 101.778,52.596 101.778,50.445 102.822,49.401 103.63,49.401 NT5E.1@103.831,49.2
NetNT5E_2: NT5E.2 R20E.2 U4E.3 | length 10
  Top Layer w0.54: NT5E.2@105.96,49.347 105.9,49.287 105.9,42.386 106.126,42.161 106.126,41.337 R20E.2@106.256,41.207 106.256,41.182 106.54,40.898 U4E.3@107.835,40.898
NetNT6A_1: NT6A.1 R31A.2 | length 2.7
  Top Layer w0.762: NT6A.1@53.371,88.883 53.497,88.883 53.625,89.01 55.824,89.01 R31A.2@55.951,89.138
NetNT6B_1: NT6B.1 R31B.2 | length 2.7
  Top Layer w0.762: NT6B.1@117.864,89.711 117.949,89.796 120.361,89.796 R31B.2@120.445,89.88
NetNT7_1: NT7.1 U2.6 | length 4.8
  Top Layer w0.254: U2.6@57.772,51.433 61.871,51.433 62.272,51.835 NT7.1@62.272,52
NetNT7_2: NT7.2 R10.1 U9.2 | length 15.4
  Top Layer w0.254: R10.1@66.048,52.641 64.738,52.641 64.304,52.208 64.304,50.927 64.812,50.419 64.812,42.179 65.972,41.02 U9.2@67.528,41.02
NetNT8A_2: NT8A.2 Q2A.5 Q2A.6 Q2A.7 Q2A.8 Q2A.9@25.572,95.718 R42A.2 R44A.2 | length 9.9
  Top Layer w0.381: R44A.2@22.651,95.653 25.507,95.653 Q2A.9@25.572,95.718
  Top Layer w0.6: R42A.2@26.399,92.289 26.399,95.118 v3(26.547,95.266)
  Top Layer w0.762: Q2A.9@25.572,95.718 25.829,95.975 26.547,95.975 NT8A.2@29.337,95.962
  other v3: 24.597,95.266 25.572,95.704 24.597,96.142 26.547,96.142 25.572,96.58
  other v12: 25.572,94.828
NetNT8B_2: NT8B.2 Q2B.5 Q2B.6 Q2B.7 Q2B.8 Q2B.9@90.065,96.547 R42B.2 R44B.2 | length 9.9
  Top Layer w0.381: R44B.2@87.144,96.482 90,96.482 Q2B.9@90.065,96.547 ; R42B.2@90.892,93.118 90.892,95.947 v3(91.04,96.095)
  Top Layer w0.762: Q2B.9@90.065,96.547 90.323,96.804 91.04,96.804 NT8B.2@93.831,96.791
  other v3: 89.09,96.095 90.065,96.533 89.09,96.971 91.04,96.971 90.065,97.409
  other v12: 90.065,95.657
NetNT9A_2: NT9A.2 Q3A.1@19.611,96.607 R42A.1 R43A.2 | length 19.9
  Top Layer w0.203: Q3A.1@19.611,96.607 19.611,94.353 21.573,92.391 R43A.2@21.573,92.289 21.662,92.2 23.286,92.2 v11(24.175,92.2) 24.91,92.2 R42A.1@24.999,92.289
  Top Layer w0.254: v16(27.496,97.631) 27.496,99.274 27.955,99.732 28.645,99.732 NT9A.2@28.958,100.045
  Mid-Layer 1 w0.203: v11(24.175,92.2) 25.926,92.2 27.496,93.771 v16(27.496,97.631)
NetNT9B_2: NT9B.2 Q3B.1@84.104,97.436 R42B.1 R43B.2 | length 20.5
  Top Layer w0.203: Q3B.1@84.104,97.436 84.104,95.182 86.066,93.22 R43B.2@86.066,93.118 86.148,93.036 89.411,93.036 R42B.1@89.492,93.118 ; 91.99,100.103 91.99,98.898 v11(92.406,98.481)
  Top Layer w0.254: 91.99,100.103 92.448,100.561 93.139,100.561 NT9B.2@93.452,100.874
  Mid-Layer 1 w0.203: v13(88.378,93.036) 88.385,93.029 90.419,93.029 92.384,94.993 92.384,98.459 v11(92.406,98.481)
NetNT12_1: NT12.1 U2.3 | length 7.5
  Top Layer w0.254: U2.3@54.566,51.427 55.519,51.427 56.496,50.45 57.694,50.45 58.932,49.212 NT12.1@61.182,49.212
NetNT12_2: NT12.2 R29.2 U9.3 | length 14.2
  Top Layer w0.254: R29.2@63.238,40.268 R29.2@63.34,40.37 ; NT12.2@63.316,49.6 63.316,49.435 63.824,48.927 63.866,48.927 64.015,48.778 64.015,41.045 R29.2@63.34,40.37 ; U9.3@67.528,40.37 R29.2@63.34,40.37
NetNT13_2: NT13.2 U3.3 | length 16.2
  Top Layer w0.254: U3.3@48.082,40.343 46.205,40.343 45.613,40.935 45.613,44.544 50.69,49.621 NT13.2@50.69,52.316
NetQ3A_3: Q3A.3@20.611,96.607 R46A.1 | length 1.9
  Top Layer w0.254: Q3A.3@20.611,96.607 20.611,96.723 21.189,97.301 R46A.1@21.189,98.258
NetQ3B_3: Q3B.3@85.104,97.436 R46B.1 | length 1.9
  Top Layer w0.254: Q3B.3@85.104,97.436 85.104,97.552 85.682,98.13 R46B.1@85.682,99.087
NetR17A_2: R17A.2 U4A.1 | length 2.5
  Top Layer w0.254: R17A.2@109.093,133.616 109.118,133.616 109.391,133.889 109.391,133.914 110.234,134.756 110.234,135.402 110.165,135.471 U4A.1@110.165,135.562
NetR17B_2: R17B.2 U4B.1 | length 2.5
  Top Layer w0.254: R17B.2@66.394,133.429 66.419,133.429 66.692,133.702 66.692,133.727 67.535,134.569 67.535,135.215 67.466,135.284 U4B.1@67.466,135.375
NetR17C_2: R17C.2 U4C.1 | length 2.5
  Top Layer w0.254: R17C.2@23.093,133.616 23.118,133.616 23.391,133.889 23.391,133.914 24.234,134.756 24.234,135.402 24.165,135.471 U4C.1@24.165,135.562
NetR17D_2: R17D.2 U4D.1 | length 2.5
  Top Layer w0.254: U4D.1@23.793,43.276 23.793,43.366 23.724,43.435 23.724,44.081 24.566,44.924 24.566,44.949 24.839,45.222 R17D.2@24.864,45.222
NetR17E_2: R17E.2 U4E.1 | length 2.5
  Top Layer w0.254: U4E.1@107.835,43.438 107.835,43.529 107.766,43.598 107.766,44.244 108.609,45.086 108.609,45.111 108.882,45.384 R17E.2@108.907,45.384
NetR19_2: R19.2 U9.1 | length 3.5
  Top Layer w0.254: R19.2@66.843,43.697 66.843,43.672 66.57,43.399 66.545,43.399 66.188,43.042 66.188,41.948 66.466,41.67 U9.1@67.528,41.67
NetR21_2: R21.2 T3.1 TP2.1 U9.6 | length 15.9
  Top Layer w0.381: U9.6@71.98,40.372 73.532,40.372 73.791,40.63 v1(73.811,40.63)
  Top Layer w0.54: v1(77.621,40.63) 78.002,40.63 78.383,41.011 80.161,41.011 ; T3.1@80.048,38.954 80.048,42.252 80.668,42.871 80.732,42.871 81.247,43.386 TP2.1@81.247,45.906
  Mid-Layer 1 w0.54: v1@73.848,40.593 v1@77.584,40.593
NetR27_2: R27.2 T3.3 TP3.1 U9.7 | length 17.6
  Top Layer w0.381: U9.7@71.978,41.02 73.094,41.02 73.43,41.356
  Top Layer w0.54: 73.43,41.356 v1(73.811,41.356) ; TP3.1@74.547,46.269 74.547,45.865 73.528,44.846 73.528,42.579 73.738,42.37 74.392,42.37 R27.2@74.522,42.24 74.547,42.24 75.716,41.071 75.716,39.702 75.714,39.701 75.714,39.256 75.413,38.954 T3.3@74.968,38.954 ; 75.716,40.975 76.859,40.975 77.367,41.482 v1(77.637,41.482)
  Mid-Layer 1 w0.54: v1(73.811,41.356) 77.51,41.356 v1(77.637,41.482)
NetR34_2: R34.2 T4.1 TP8.1 U3.6 | length 17.8
  Top Layer w0.381: U3.6@52.532,40.343 54.12,40.343 54.344,40.567 v1(54.365,40.567)
  Top Layer w0.54: v1(58.175,40.567) 58.556,40.567 58.937,40.948 60.715,40.948 60.741,40.974 ; T4.1@60.715,38.949 60.741,38.974 60.741,40.974 ; TP8.1@60.848,46.792 60.848,46.419 61.952,45.315 61.952,43.445 61.742,43.235 60.898,43.235 R34.2@60.768,43.105 60.768,43.002 60.741,42.975 60.741,40.974
  Mid-Layer 1 w0.54: v1(54.365,40.567) v1(58.175,40.567)
NetR34A_1: R34A.1 R145A.2 U11A.7 | length 3.5
  Top Layer w0.254: U11A.7@55.874,109.255 55.874,110.459 56.149,110.734 56.13,110.752 R145A.2@56.13,112.618
NetR34B_1: R34B.1 R145B.2 U11B.7 | length 3.5
  Top Layer w0.254: U11B.7@110.92,113.582 110.92,114.786 111.195,115.061 111.177,115.079 R145B.2@111.177,116.945
NetR35_2: R35.2 T4.3 TP9.1 U3.7 | length 18.1
  Top Layer w0.381: U3.7@52.532,40.993 53.648,40.993 53.984,41.329
  Top Layer w0.54: TP9.1@53.806,46.965 TP9.1@54.09,47.249 54.09,44.012 54.982,43.121 55.307,43.121 R35.2@55.437,42.99 ; 53.984,41.329 v1(54.365,41.329) ; R35.2@55.332,43.121 55.988,42.464 55.988,41.23 56.27,40.948 ; T4.3@55.635,38.949 55.635,40.314 56.27,40.948 ; v1(58.175,41.329) 57.794,41.329 57.413,40.948 56.27,40.948
  Mid-Layer 1 w0.54: v1(54.365,41.329) v1(58.175,41.329)
NetR37A_1: R37A.1 R38A.2 U8A.1 | length 4.3
  Top Layer w0.254: U8A.1@43.531,97.086 43.531,99.001 43.785,99.255 R38A.2@43.785,100.144 R37A.1@44.921,100.144
NetR37B_1: R37B.1 R38B.2 U8B.1 | length 4.3
  Top Layer w0.254: U8B.1@108.025,97.915 108.025,99.829 108.279,100.083 R38B.2@108.279,100.973 R37B.1@109.415,100.973
NetR38A_1: R38A.1 R39A.2 U8A.2 | length 4.6
  Top Layer w0.229: R39A.2@42.39,101.541 42.385,101.535 R38A.1@42.385,100.144 42.385,99.601 43.056,98.93 43.056,97.236 U8A.2@43.056,97.234
NetR38B_1: R38B.1 R39B.2 U8B.2 | length 4.6
  Top Layer w0.229: R39B.2@106.884,102.369 106.879,102.364 R38B.1@106.879,100.973 106.879,100.43 107.55,99.759 107.55,98.065 U8B.2@107.55,98.062
NetR40A_1: R40A.1 U14A.11 | length 1.9
  Top Layer w0.254: R40A.1@67.177,102.723 67.225,102.771 67.225,102.932 67.805,103.511 67.805,104.299 U14A.11@67.853,104.347
NetR40A_2: R40A.2 U14A.12 | length 2.2
  Top Layer w0.254: R40A.2@67.827,102.723 67.827,102.718 68.241,102.718 68.503,102.98 U14A.12@68.503,104.347
NetR40B_1: R40B.1 U14B.11 | length 2
  Top Layer w0.254: R40B.1@122.174,106.968 122.222,107.016 122.222,107.171 122.322,107.271 122.322,107.274 122.543,107.495 122.546,107.495 122.851,107.801 122.851,108.626 U14B.11@122.899,108.674
NetR40B_2: R40B.2 U14B.12 | length 2.3
  Top Layer w0.254: R40B.2@122.824,106.968 123.38,106.968 123.549,107.138 U14B.12@123.549,108.674
NetR45A_2: R45A.2 TP35AA.1 U8A.9 | length 17.2
  Top Layer w0.229: U8A.9@43.067,95.423 43.067,95.01 43.366,94.711 43.366,93.75 v1(43.085,93.47) R45A.2@43.085,92.589
  Mid-Layer 2 w0.229: v1(43.085,93.47) 43.085,92.411 51.455,84.041 51.455,83.345 TP35AA.1@51.8,83
NetR45B_2: R45B.2 TP35AB.1 U8B.9 | length 17
  Top Layer w0.229: U8B.9@107.56,96.251 107.56,95.839 107.859,95.54 107.859,94.579 v1(107.579,94.298) R45B.2@107.579,93.417
  Mid-Layer 1 w0.229: v1(107.579,94.298) 107.579,93.239 115.674,85.144
  Mid-Layer 1 w0.254: 115.674,85.144 116.856,85.144 TP35AB.1@117,85
NetR47A_1: R47A.1 R48A.2 U8A.4 | length 4.4
  Top Layer w0.254: R47A.1@40.789,97.881 R48A.2@40.789,99.255 41.289,99.255 42.081,98.463 U8A.4@42.081,97.086
NetR47B_1: R47B.1 R48B.2 U8B.4 | length 4.4
  Top Layer w0.254: R47B.1@105.283,98.71 R48B.2@105.283,100.083 105.783,100.083 106.575,99.291 U8B.4@106.575,97.915
NetR149A_1: R149A.1 U11A.6 | length 15.2
  Top Layer w0.254: R149A.1@51.986,110.569 51.966,110.569 51.883,110.652 51.883,110.672 51.563,110.992 51.563,112.827 53.015,114.279 57.075,114.279 58.723,112.631 58.723,111.429 56.549,109.255 U11A.6@56.536,109.255
NetR149B_1: R149B.1 U11B.6 | length 11.3
  Top Layer w0.254: R149B.1@107.033,114.896 107.056,114.92 107.056,116.651 108.128,117.722 111.563,117.722 112.047,117.238 112.047,114.034 111.595,113.582 U11B.6@111.583,113.582
PRU0_PERIF0_IN: J2.15 R17A.1 | length 97.8
  Top Layer w0.254: v1(108.819,130.741) 109.093,131.015 R17A.1@109.093,132.216
  Mid-Layer 1 w0.54: J2.15@29.037,112.107 27.792,110.862 27.792,109.051 30.957,105.886 49.373,105.886 v4(60.508,117.022)
  Mid-Layer 2 w0.54: v4(60.508,117.022) 62.767,117.022 62.793,117.047 79.642,117.047 89,126.405 97.305,126.405 101.64,130.741 v1(108.819,130.741)
PRU0_PERIF1_IN: J2.14 R17B.1 | length 47.1
  Top Layer w0.254: v1(66.12,130.554) 66.394,130.828 R17B.1@66.394,132.029
  Top Layer w0.54: J2.14@31.577,112.107 31.577,115.464 34.814,118.701 35.427,118.701 40.834,124.108 v2(40.834,126.499)
  Mid-Layer 1 w0.54: v2(40.834,126.499) 51.97,126.499 52.99,127.518 63.084,127.518 v1(66.12,130.554)
PRU0_PERIF2_IN: J5.43 R17C.1 | length 127.3
  Top Layer w0.54: v1(22.819,130.741) 23.093,131.015 R17C.1@23.093,132.216
  Mid-Layer 1 w0.54: v1(22.819,130.741) 22.819,123.205 26.024,120 70.491,120 76.798,113.693 76.798,63.904 77.114,63.588 83.843,63.588 84.917,64.661 J5.43@84.917,66.387
PRU0_PERIF2_OUT: R50.1 U4C.4 | length 112.6
  Top Layer w0.254: U4C.4@24.165,139.372 v1(25.377,139.372)
  Top Layer w0.54: v2(24.984,62.272) R50.1@24.984,64.129 ; v2(41.48,104.299) 43.97,106.788 43.97,126.602 v2(41.48,129.091)
  Mid-Layer 1 w0.54: v2(24.984,62.272) 38.637,62.272 41.067,64.702 41.067,69.812 39.021,71.858 39.021,96.246 41.48,98.705 v2(41.48,104.299) ; v1(25.377,139.372) 37.613,139.372 41.509,135.476 41.509,129.12 v2(41.48,129.091)
PRU1_PERIF0_OUT_EN: R60.2 U10D.2 U10D.5 | length 94.7
  Top Layer w0.254: U10D.2@16.531,53.666 17.459,53.666 18.459,52.666 U10D.5@19.731,52.666 19.808,52.666 19.829,52.645 v2(19.829,51.64)
  Top Layer w0.54: v2(21.039,55.276) 54.077,55.276 v4(56.801,58) ; R60.2@97.617,72.511 v4(97.617,73.88)
  Mid-Layer 1 w0.54: v2(19.829,51.64) 21.039,52.85 v2(21.039,55.276)
  Mid-Layer 2 w0.54: v4(56.801,58) 56.863,57.938 57.539,57.938 57.685,57.791 58.837,57.791 74.408,73.362 74.98,73.362 75.459,73.842 76,73.842 76.038,73.88 v4(97.617,73.88)
PRU1_PERIF2_CLK: R9E.1 R61.2 U5E.4 | length 43.3
  Top Layer w0.254: R9E.1@90.066,37.938 U5E.4@90.066,39.608
  Top Layer w0.54: v2(87.962,40.209) 87.962,40.178 88.532,39.608 U5E.4@90.066,39.608 ; R61.2@100.207,72.511 100.337,72.381 101.046,72.381 101.414,72.013 v2(101.502,72.013)
  Mid-Layer 1 w0.54: v2(87.962,40.209) 87.962,40.297 87.503,40.756 87.503,48.594 101.452,62.543 101.452,71.963 v2(101.502,72.013)
PRU1_PERIF2_IN: J5.70 R17E.1 | length 25.5
  Top Layer w0.254: R17E.1@108.907,46.784 108.907,47.985 v1(109.181,48.259)
  Mid-Layer 1 w0.54: J5.70@102.697,68.927 102.839,68.785 103.716,68.785 104.936,67.564 104.936,57.484 109.181,53.24 v1(109.181,48.259)
PRU1_PERIF2_OUT: R62.1 U4E.4 | length 83.7
  Top Layer w0.254: R62.1@98.793,107.3 R62.1@98.797,107.296
  Top Layer w0.54: v2(97.617,107.3) R62.1@98.793,107.3 ; v1(106.623,39.628) U4E.4@107.835,39.628
  Mid-Layer 1 w0.54: v2(97.617,107.3) 97.617,107.293 97.046,106.722 97.046,78.137 100.681,74.502 108.852,74.502 110.631,72.724 110.631,41.318 108.941,39.628 v1(106.623,39.628)
PRU_PERIF_OUT_EN_2: J16.1 J16.2 U2.2 U2.5 | length 14.1
  Top Layer w0.254: U2.2@54.566,51.927 55.666,51.927 56.666,50.927 58.646,50.927 v2(59.576,49.997) ; J16.1@60.548,55.344 J16.2@63.088,55.344
  Mid-Layer 1 w0.254: v2(59.576,49.997) 59.576,50.646 60.547,51.617 60.547,55.343 J16.1@60.548,55.344
PRU_PERIF_OUT_ENE: J18.2 U10E.2 U10E.5 | length 18.4
  Top Layer w0.254: U10E.2@100.573,53.828 101.502,53.828 102.502,52.828 U10E.5@103.773,52.828 104.01,52.828 104.032,52.807 104.032,52.57 104.17,52.431 v4(104.17,51.611)
  Mid-Layer 2 w0.381: v4(104.17,51.611) 106.146,53.586 114.98,53.586 J18.2@116.146,52.42
RS485_EN_HIGH: NT2A.1 NT2B.1 NT2C.1 NT2D.1 NT2E.1 NT13.1 R12.1 U2.1 U2.7 U10A.1 U10A.7 U10B.1 U10B.7 U10C.1 U10C.7 U10D.1 U10D.7 U10E.1 U10E.7 | length 305.7
  Top Layer w0.254: NT2D.1@13.422,53.666 13.922,54.166 U10D.1@16.531,54.166 17.876,54.166 18.376,53.666 U10D.7@19.731,53.666 19.722,53.675 19.297,53.675 17.33,55.642 17.33,56.44 v4(17.315,56.455) ; U10C.7@28.227,125.172 29.582,125.172 30.082,124.672 U10C.1@31.427,124.672 34.036,124.672 NT2C.1@34.536,125.172 34.653,125.289 34.653,126.097 35.636,127.081 35.842,127.081 v2(35.958,127.197) ; NT13.1@52.722,52.316 53.738,52.316 53.849,52.427 55.911,52.427 56.411,51.927 U2.7@57.766,51.927 ; U2.1@54.53,52.418 U2.1@54.542,52.406 ; U2.1@54.542,52.404 v4(54.542,54.116) 57.478,57.052 64.324,57.052 68.425,52.951 68.425,51.205 68.971,50.659 71.542,50.659 78.209,57.326 96.363,57.326 97.347,56.342 ; v4(68.312,125.095) 68.413,124.993 71.519,124.993 U10B.7@71.528,124.985 72.882,124.985 73.382,124.485 U10B.1@74.728,124.485 77.336,124.485 NT2B.1@77.836,124.985 77.925,124.896 v2(77.925,123.375) ; NT2E.1@97.347,53.946 97.347,56.342 ; NT2E.1@97.882,54.411 97.464,53.994 NT2E.1@97.464,53.828 97.964,54.328 U10E.1@100.573,54.328 101.918,54.328 102.418,53.828 U10E.7@103.773,53.828 ; v4(101.554,57.562) 101.438,57.445 98.45,57.445 97.347,56.342 ; v4@105.935,70.24 105.935,70.474 v4(105.819,70.591) 107.432,70.591 R12.1@107.483,70.641 R12.1@107.483,70.666 ; v4(106.637,120.81) 106.802,120.81 106.992,121 116.364,121 119.863,124.498 120.028,124.498 120.536,125.006 NT2A.1@120.536,125.172 120.036,124.672 U10A.1@117.427,124.672 115.898,124.672 115.648,124.922 115.461,124.922 115.211,125.172 U10A.7@114.227,125.172
  Mid-Layer 1 w0.254: v2(35.958,127.197) 37.415,125.74 61.166,125.74 v4(61.195,125.77) ; v2(77.925,123.375) 79.472,124.922 v15@115.555,124.922
  Mid-Layer 2 w0.254: v4(17.315,56.455) 52.203,56.455 v4(54.542,54.116) ; v4(61.195,125.77) 61.228,125.77 61.903,125.095 v4(68.312,125.095) ; v4(101.554,57.562) 101.554,61.944 105.819,66.208 v4(105.819,70.591) 103.855,72.554 103.855,97.2 106.637,99.982 v4(106.637,120.81)
  other v15: 115.521,125.064
V_BULKA: C20A.1 C28A.1 C29A.1 C30A.1 D9A.1 J11A.2 NT8A.1 R36A.1 R47A.2 TP37A.1 U8A.6 | length 57.1
  Top Layer w0.292: 40.552,96.086 U8A.6@42.831,96.086
  Top Layer w0.762: C20A.1@20.711,85.871 20.711,86.305 C20A.1@20.757,86.35 ; NT8A.1@31.369,95.797 NT8A.1@31.369,95.962 33.594,95.962 D9A.1@36.381,93.176 ; C29A.1@32.464,85.871 32.787,85.871 32.787,91.973 33.99,93.176 D9A.1@36.381,93.176 ; D9A.1@36.735,93.176 D9A.1@36.381,93.176 ; C28A.1@44.217,85.871 44.217,84.821 47.668,81.37 50.197,81.37 TP37A.1@51.8,79.768 ; v4(46.821,95.642) 46.849,95.642 47.05,95.843 J11A.2@49.647,95.843
  Top Layer w1.27: C20A.1@20.711,85.871 32.787,85.871 C28A.1@44.217,85.871
  other v8: 41.815,96.086 42.442,96.086 43.07,96.086 43.697,96.086
V_BULKB: C20B.1 C28B.1 C29B.1 C30B.1 D9B.1 J11B.2 NT8B.1 R36B.1 R47B.2 TP37B.1 U8B.6 | length 82.8
  Top Layer w0.254: 115.308,81.112 115.378,81.182
  Top Layer w0.292: R47B.2@103.616,98.686 103.616,98.661 105.045,97.232 105.045,96.915 v8(106.309,96.915)
  Top Layer w0.762: C29B.1@97.281,86.7 97.281,92.801 98.484,94.005 ; v6(101.225,96.334) 101.225,94.008 D9B.1@101.229,94.005 ; R47B.2@103.616,98.686 102.178,98.686 101.732,99.133 101.732,99.158 101.506,99.383 R36B.1@101.481,99.383 98.455,99.383 96.282,97.21 96.117,97.21 95.863,96.956 NT8B.1@95.863,96.791 95.863,96.626 98.484,94.005 ; C30B.1@105.048,94.876 105.048,94.851 103.951,93.755 101.398,93.755 101.229,93.924 D9B.1@101.229,94.005 ; C28B.1@108.711,86.7 108.711,85.65 109.33,85.031 111.389,85.031 115.308,81.112 ; v4(111.315,96.47) 111.342,96.47 111.543,96.671 J11B.2@114.141,96.671 ; 115.378,81.182 TP37B.1@117,81.182 ; 98.484,94.005 D9B.1@101.229,94.005
  Top Layer w1.27: C20B.1@85.205,86.7 C29B.1@96.958,86.7 97.281,86.7 C28B.1@108.711,86.7
  Bottom Layer w0.762: v6(101.225,96.334) 102.3,95.258 110.103,95.258 v4(111.315,96.47)
  other v8: 106.955,96.92 107.563,96.915 108.19,96.915
VOUT_5V0_ENC_A: C114A.1 J3A.6 J3B.6 J3C.6 R34A.2 R149A.2 U11A.9 U11A.10 | length 210
  Top Layer w0.254: U11A.9@54.874,109.255 R34A.2@54.874,110.459
  Top Layer w0.4: R149A.2@52.646,110.569 53.176,110.569
  Top Layer w0.508: C114A.1@52.461,109.055 53.066,109.66 53.066,110.459 53.176,110.569 53.312,110.704 R34A.2@54.425,110.704 ; C114A.1@52.682,109.255 U11A.10@54.211,109.255
  Top Layer w1: v6(52.9,112.229) 54.425,110.704 R34A.2@54.569,110.704
  Bottom Layer w1: v6(52.9,112.229) 54.728,110.401 55.696,110.401 57.524,108.573 57.524,90.708 55.867,89.052 52.316,89.052 44.217,80.953 44.217,38.123 29.115,23.021 J3A.6@29.115,7.181 29.268,7.334 29.268,8.811 30.039,9.581 64.042,9.581 J3B.6@66.591,7.032 69.141,9.581 101.576,9.581 J3C.6@104.067,7.09
VOUT_5V0_ENC_B: C114B.1 J3D.6 J3E.6 J3F.6 R34B.2 R149B.2 U11B.9 U11B.10 | length 150.3
  Top Layer w0.254: R34B.2@109.645,115.061 109.92,114.786 U11B.9@109.92,113.582
  Top Layer w0.4: R149B.2@107.693,114.896 108.223,114.896
  Top Layer w0.508: C114B.1@107.508,113.382 108.113,113.987 108.113,114.786 108.223,114.896 108.358,115.032 109.616,115.032 R34B.2@109.645,115.061 ; C114B.1@107.729,113.582 U11B.10@109.258,113.582
  Top Layer w1: v10(104.46,126.56) 104.46,114.64 v6(105.748,113.353) 105.752,113.357 C114B.1@107.508,113.357
  Mid-Layer 1 w1: J3D.6@100.567,172 100.567,167.056 106.169,161.453 106.169,129.613 104.46,127.904 v10(104.46,126.56)
  Bottom Layer w1: J3F.6@25.615,172 28.315,169.3 60.391,169.3 J3E.6@63.091,172 65.791,169.3 97.867,169.3 J3D.6@100.567,172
